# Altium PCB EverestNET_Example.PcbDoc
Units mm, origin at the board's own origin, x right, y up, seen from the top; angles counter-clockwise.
Board outline 100 x 100 mm, 6 copper layers (Top Layer, Mid-Layer 1, Mid-Layer 2, Mid-Layer 3, Mid-Layer 4, Bottom Layer), stack 1.62 mm thick; 18 components, 58 nets, 312 pads, 51 vias.
Unrouted connection lines stored in the file: 9.
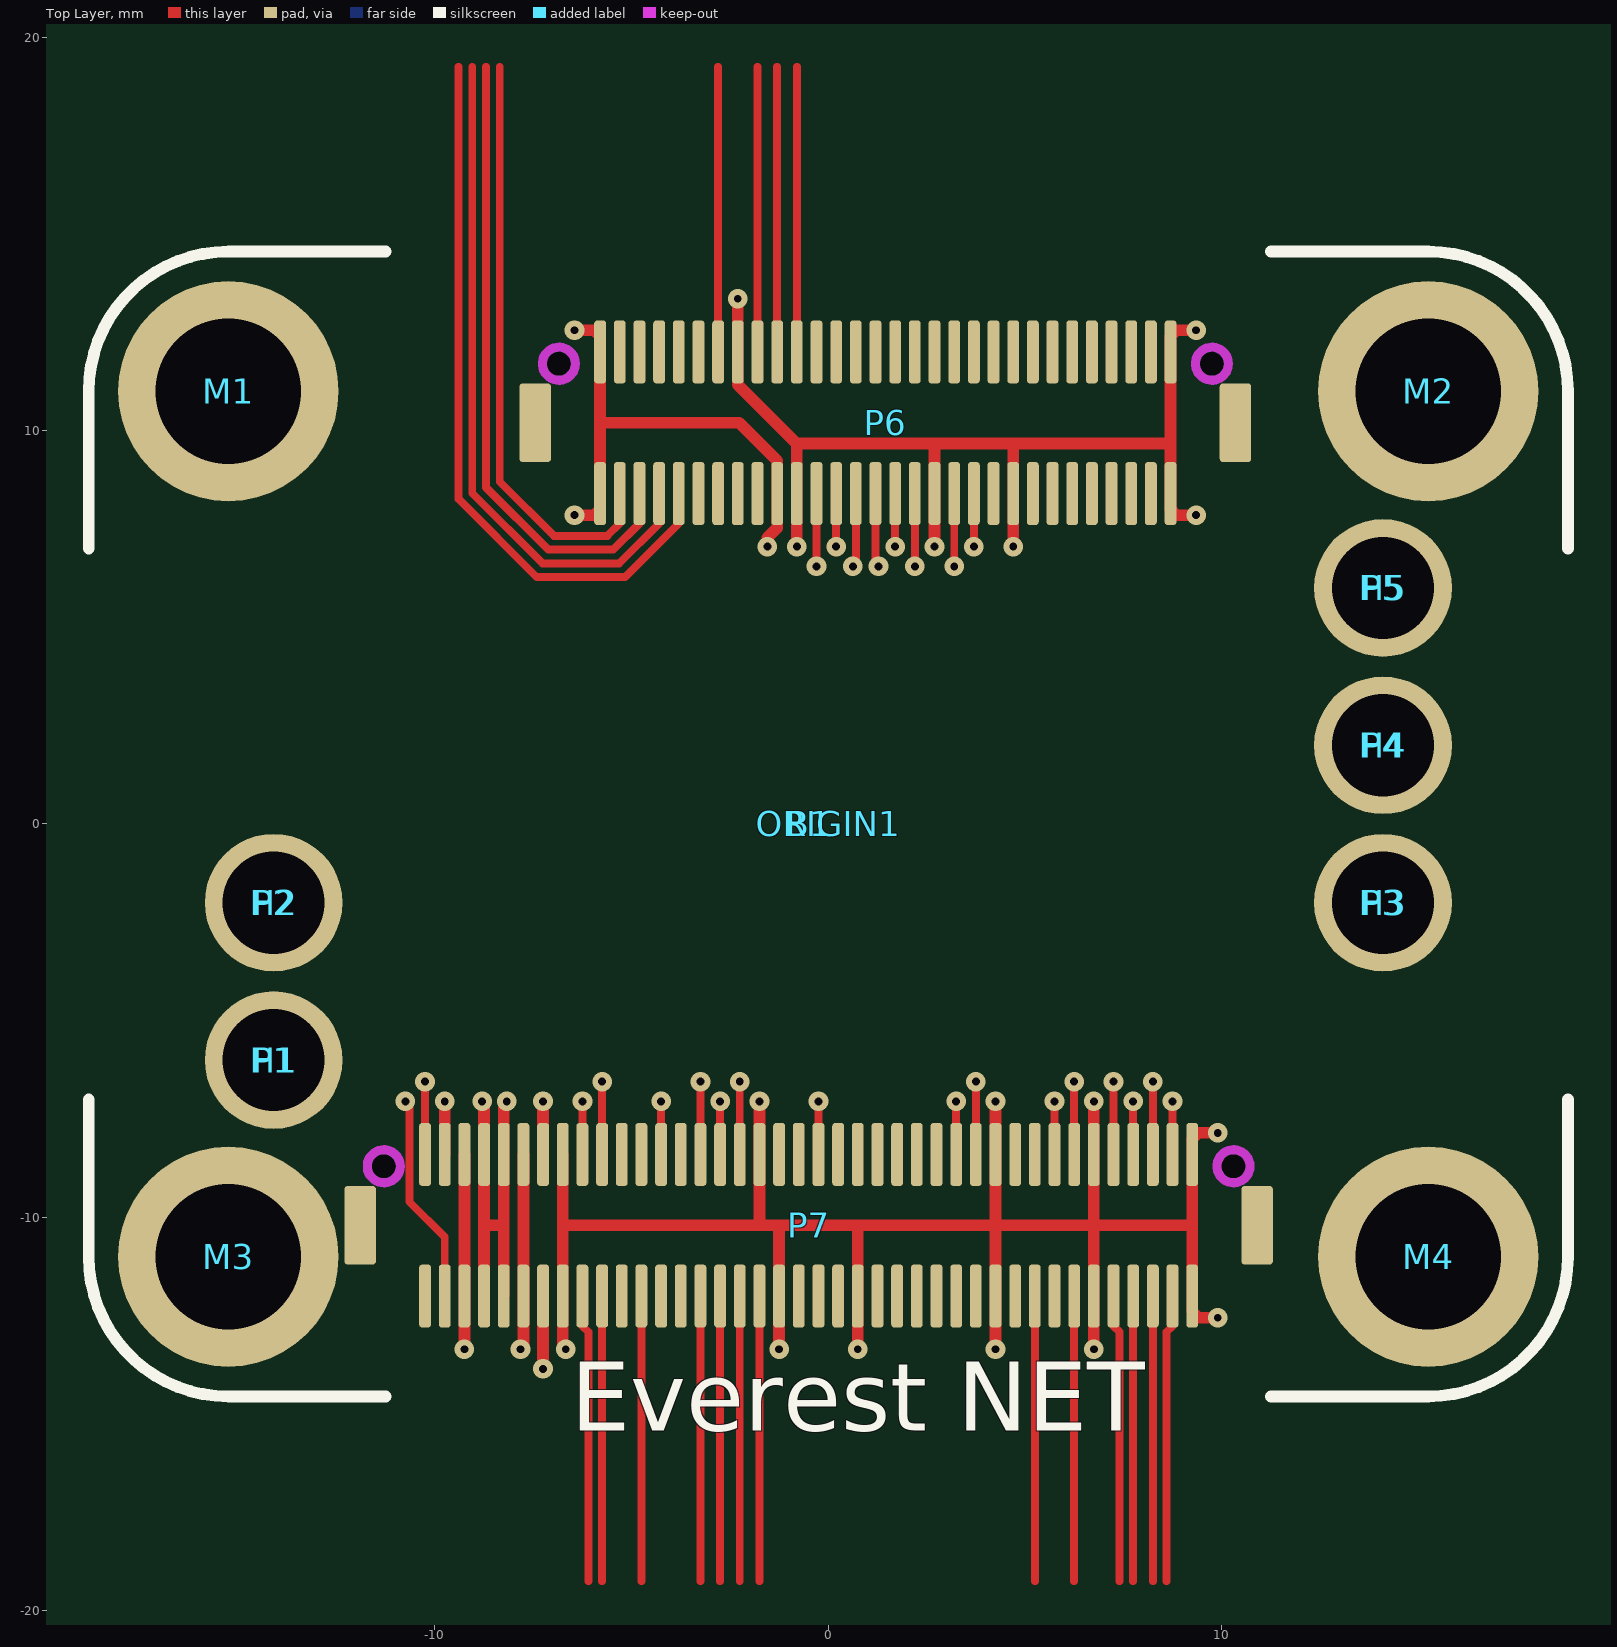
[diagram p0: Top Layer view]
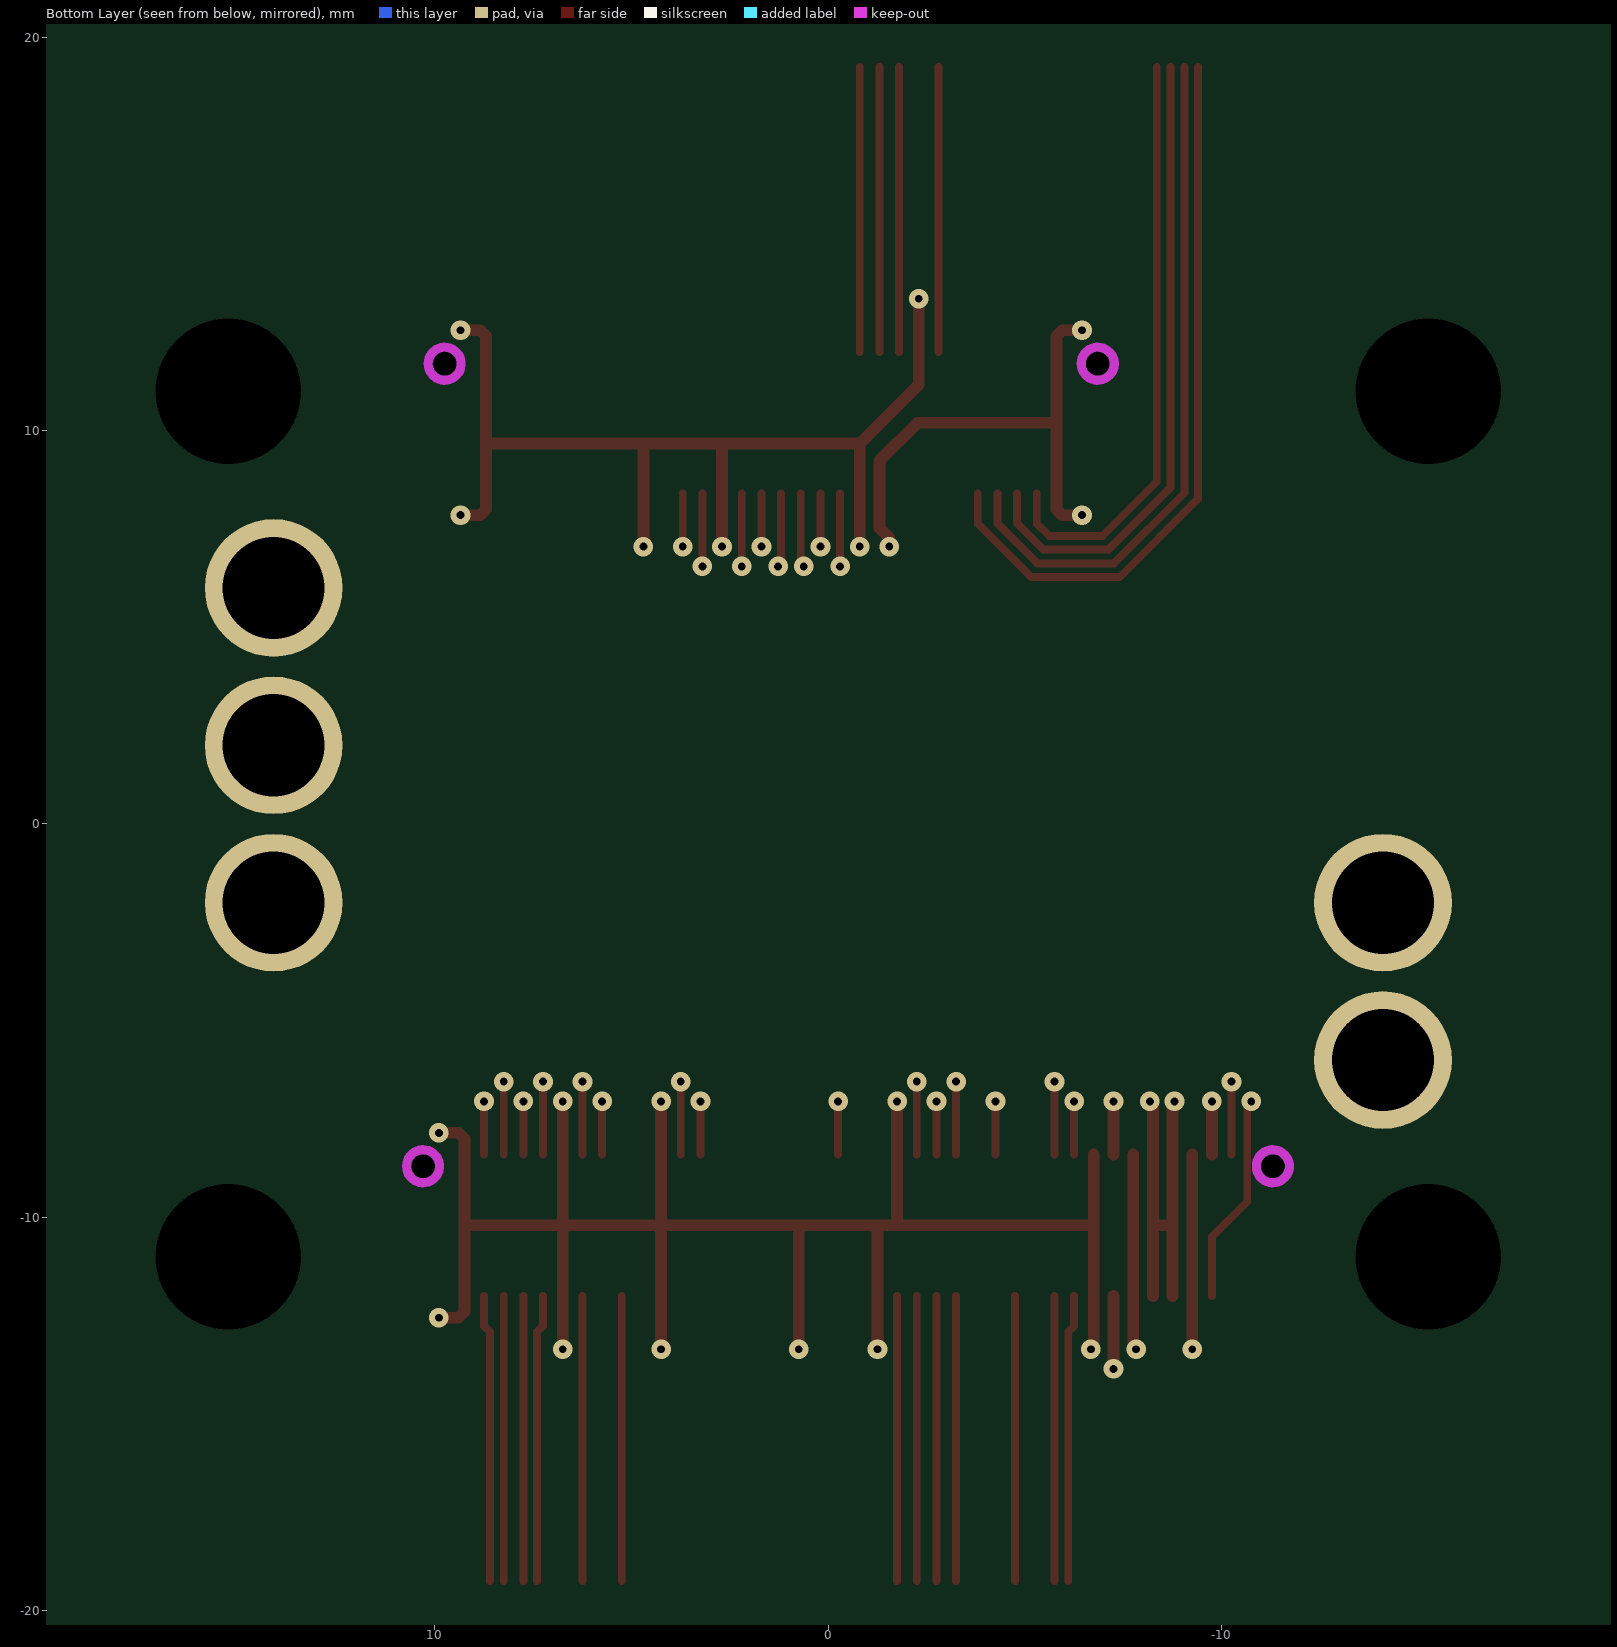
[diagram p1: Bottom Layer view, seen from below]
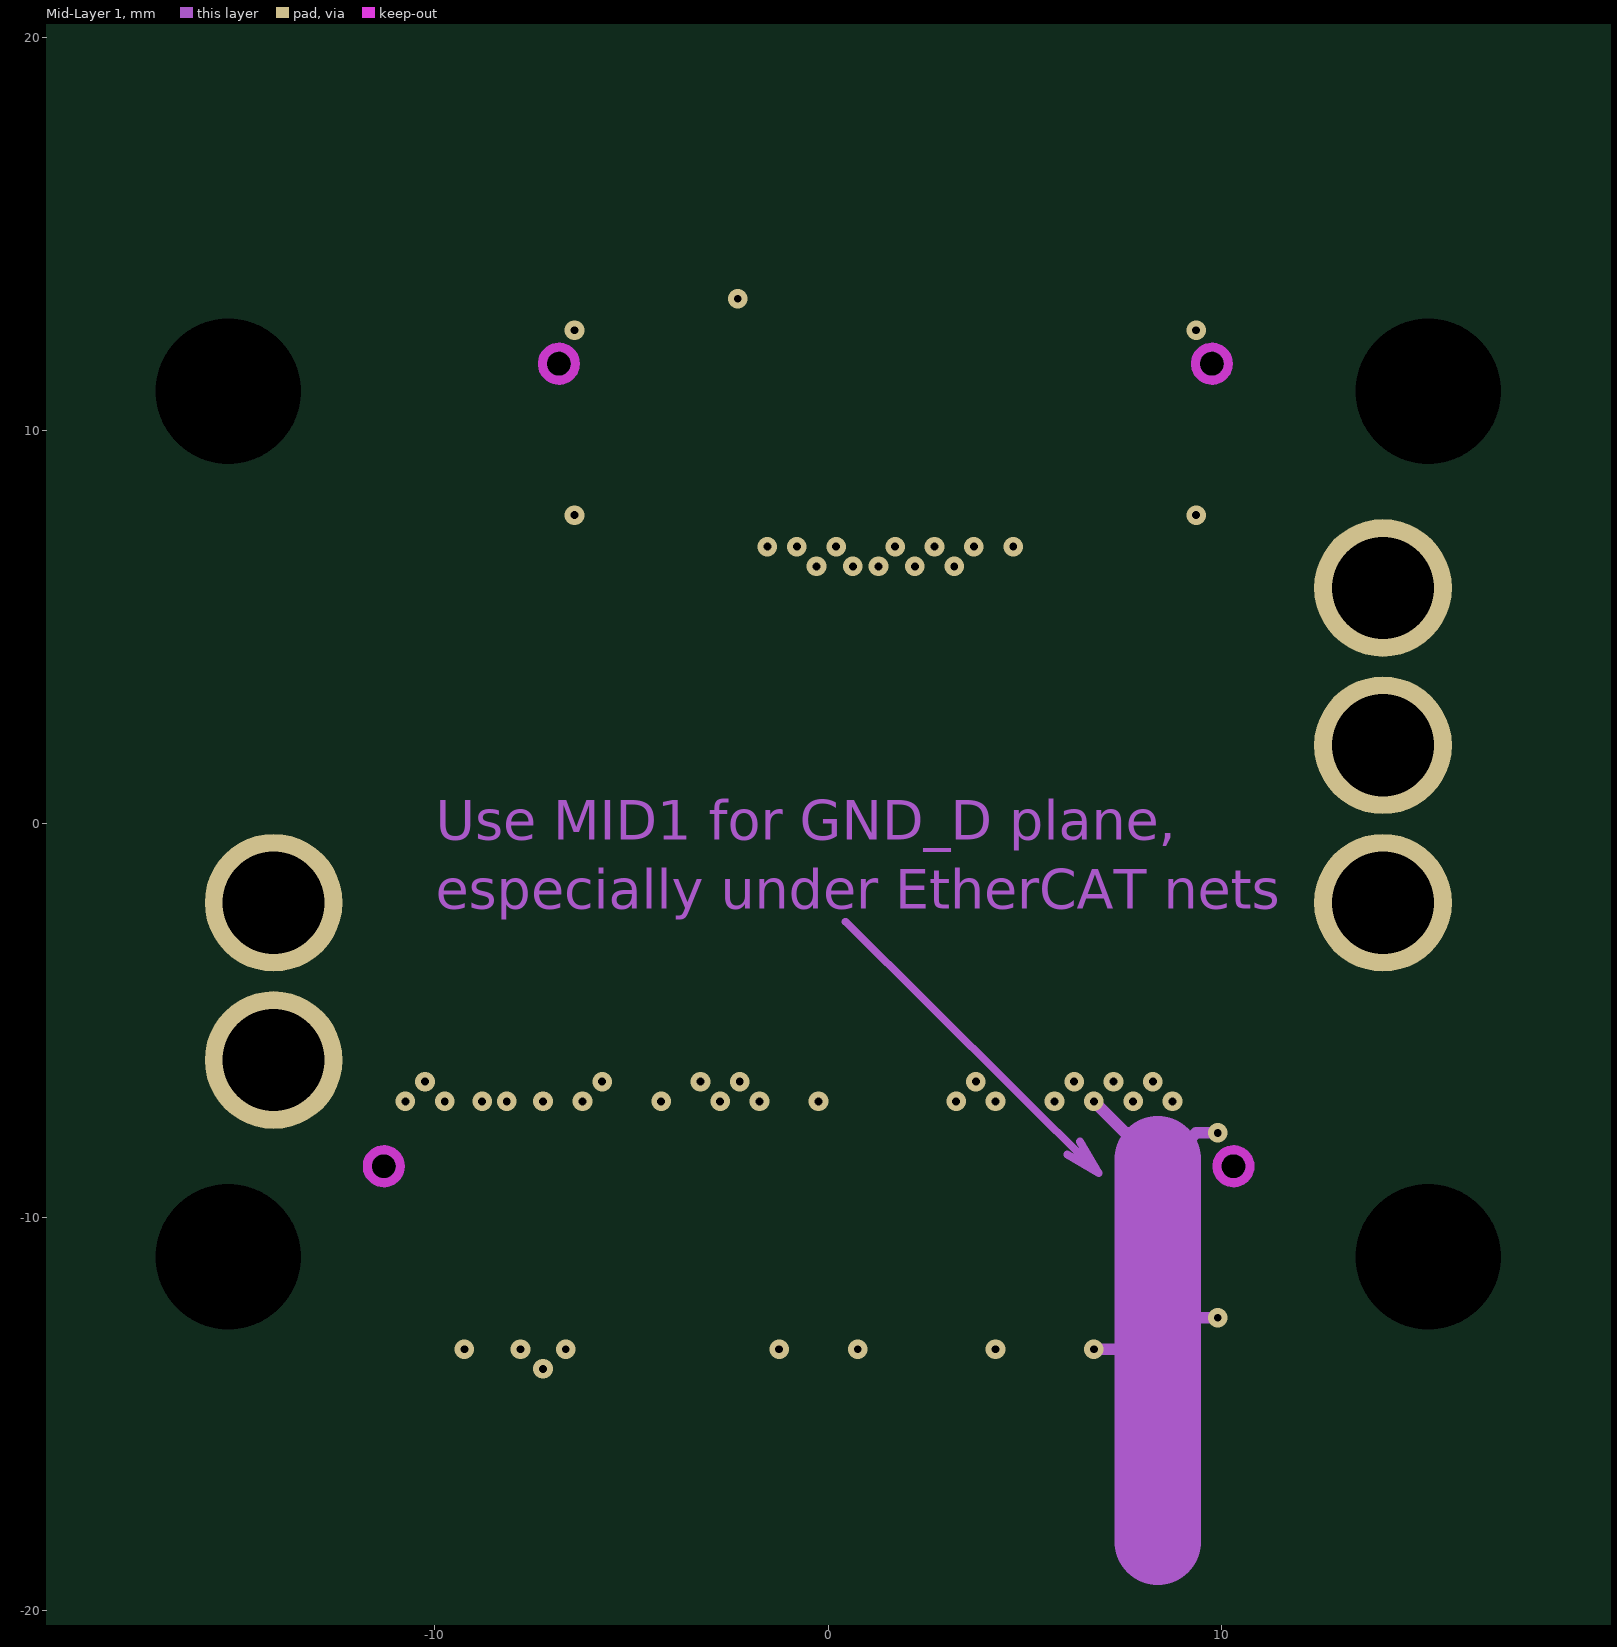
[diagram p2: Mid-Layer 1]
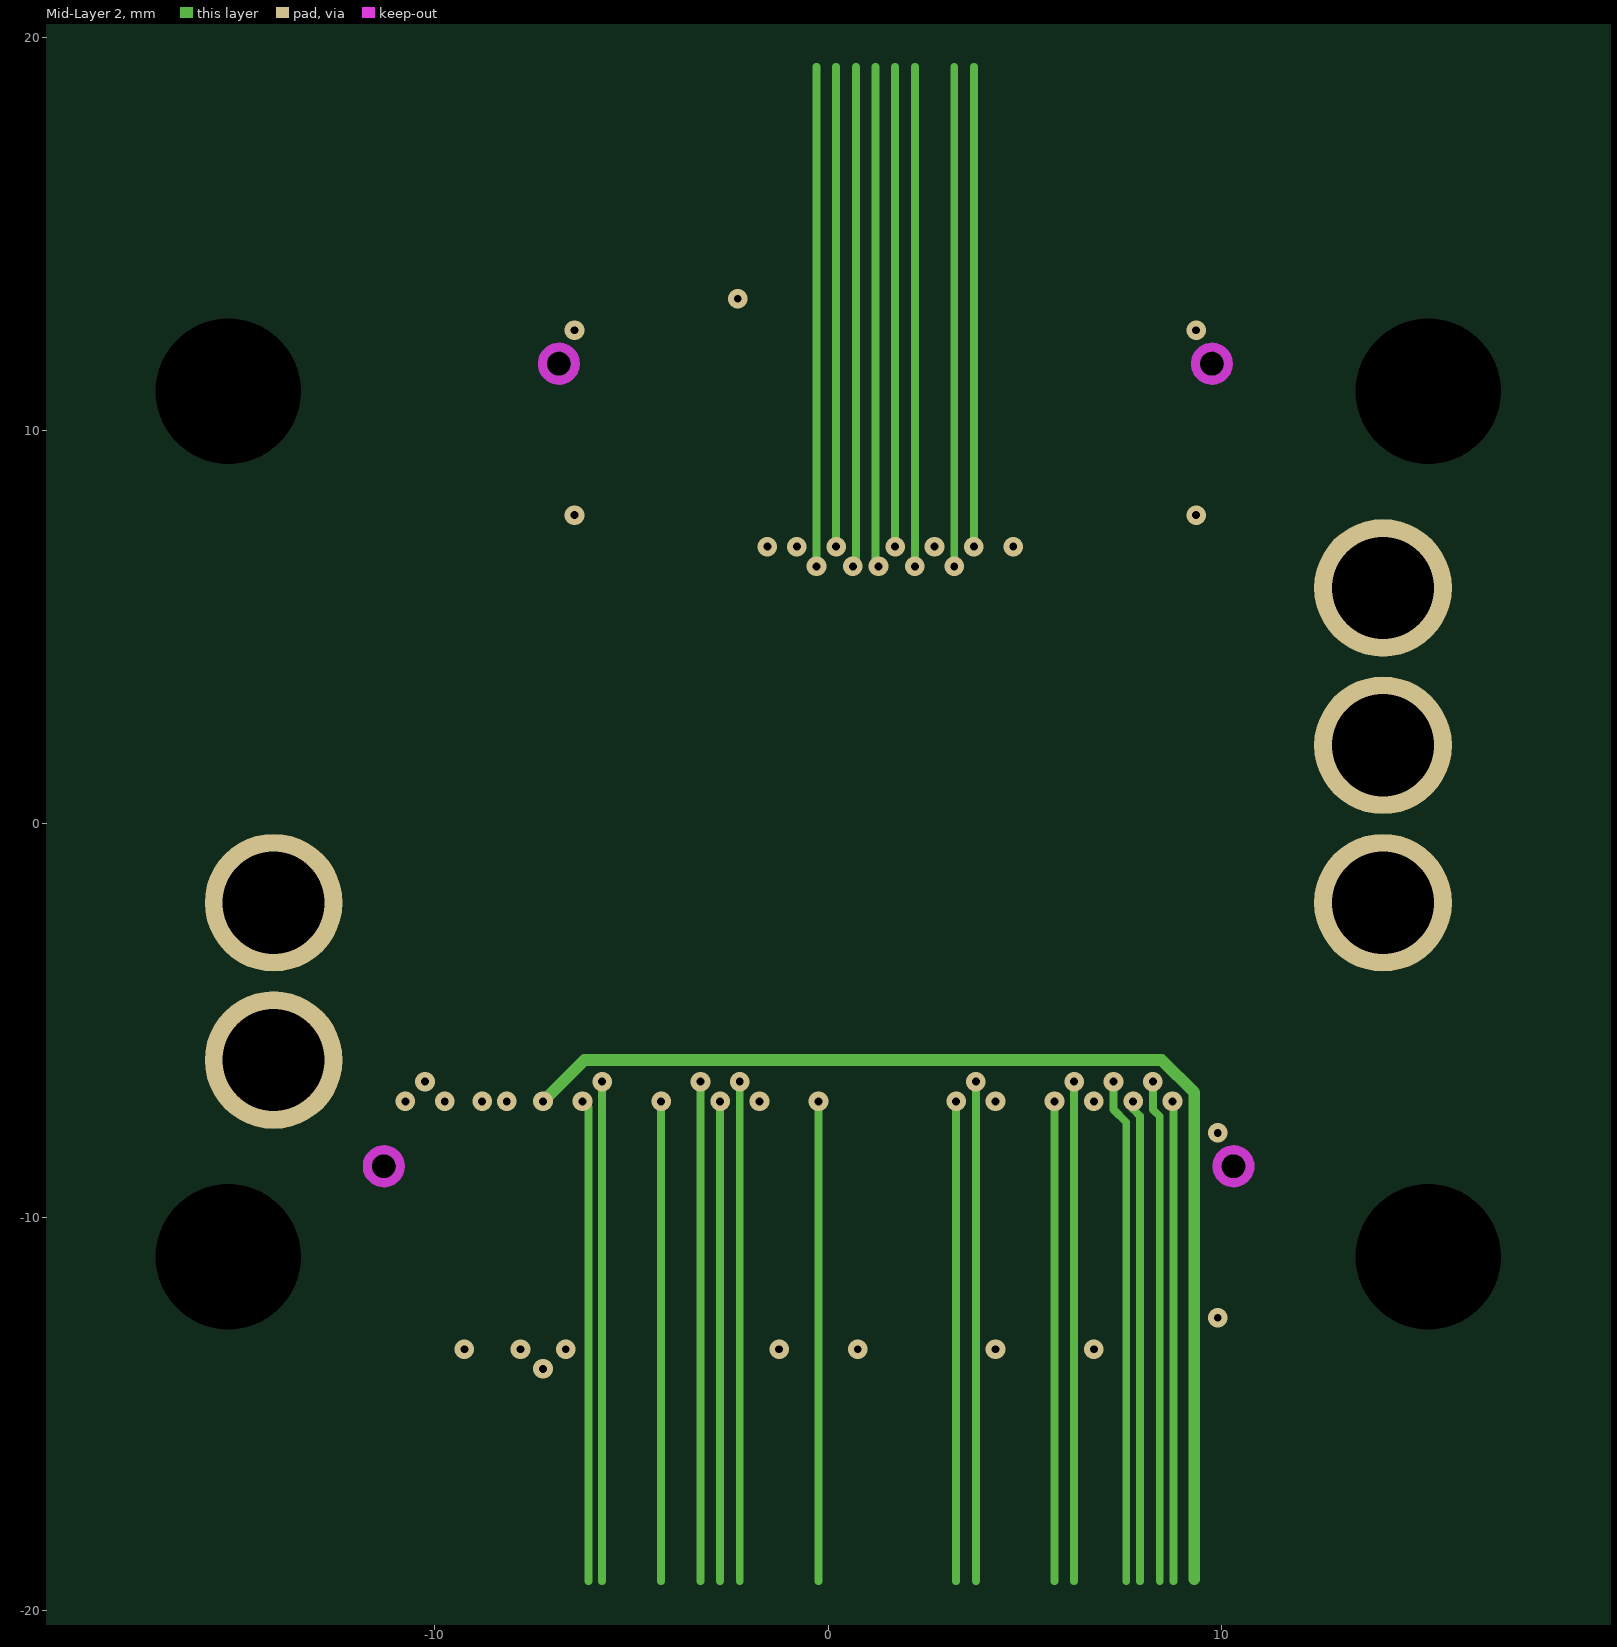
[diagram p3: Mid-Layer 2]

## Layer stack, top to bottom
Top Solder: solder mask 0.005, Solder Resist, Dk 3.5
Top Layer: signal copper 0.06
Dielectric 1: prepreg 0.22, FR-4 (tg > 150C), Dk 4.2
Mid-Layer 1: signal copper 0.035
Dielectric 2: core 0.35, FR-4 (tg > 150C), Dk 4.2
Mid-Layer 2: signal copper 0.035
Dielectric 3: prepreg 0.22, FR-4 (tg > 150C), Dk 4.2
Mid-Layer 3: signal copper 0.035
Dielectric 4: core 0.35, FR-4 (tg > 150C), Dk 4.2
Mid-Layer 4: signal copper 0.035
Dielectric 5: prepreg 0.22, FR-4 (tg > 150C), Dk 4.2
Bottom Layer: signal copper 0.06
Bottom Solder: solder mask 0.005, Solder Resist, Dk 3.5

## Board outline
-50.125,-47.425 49.875,-47.425 49.875,52.575 -50.125,52.575

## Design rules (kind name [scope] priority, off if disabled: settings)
AssemblyTestPointUsage [All] p1 off: valid=2
AssemblyTestpoint [All] p1 off: testpointundercomponent=TRUE minsize=1.016 maxsize=2.54 preferedsize=1.524 minholesize=0 maxholesize=1.016 preferedholesize=0.813 testpointgrid=0.025 usegrid=TRUE gridtolerance=0 allowsidetop=TRUE allowsidebottom=TRUE
Clearance "Keepout clearance" [All vs OnLayer('Keep-Out Layer') Or IsKeepOut Or Keepout] p1: gap=0.001 ignorepadtopadclearanceinfootprint=FALSE
Clearance HV [InNetClass('HighVoltage') vs OnOutside And NOT InNetClass('HighVoltageFloating')] p2: gap=0.5 ignorepadtopadclearanceinfootprint=TRUE
Clearance Clearance_PE [InNetClass('ProtectiveEarth')] p3: gap=0.5 ignorepadtopadclearanceinfootprint=TRUE
Clearance General [All] p4: gap=0.15 ignorepadtopadclearanceinfootprint=TRUE
ComponentClearance ComponentClearance_Excluded [All vs InComponent ('B1') OR InComponent('P1') OR InComponent('P2') OR InComponent('P3') OR InComponent('P4') OR InComponent('P5') OR InComponent('P6') OR InComponent('P7') OR InComponent('H1') OR InComponent('H2') OR InComponent('H3') OR InComponent('H4') OR InComponent('H5') OR InComponent('M1') OR InComponent('M2') OR InComponent('M3') OR InComponent('M4')] p1: gap=0 collisioncheckmode=3 verticalgap=0 showdistances=FALSE
ComponentClearance [All] p2: gap=0.2 collisioncheckmode=3 verticalgap=0.2 showdistances=FALSE
DiffPairsRouting [All] p1: maxlimit=1 minlimit=0.15 mostfreqgap=0.2 toplayer_minwidth=0.15 toplayer_maxwidth=0.3 toplayer_prefwidth=0.2 midlayer1_minwidth=0.15 midlayer1_maxwidth=0.3 midlayer1_prefwidth=0.2 midlayer2_minwidth=0.15 midlayer2_maxwidth=0.3 midlayer2_prefwidth=0.2 midlayer3_minwidth=0.15 midlayer3_maxwidth=0.3 midlayer3_prefwidth=0.2 midlayer4_minwidth=0.15 midlayer4_maxwidth=0.3 midlayer4_prefwidth=0.2 bottomlayer_minwidth=0.15 bottomlayer_maxwidth=0.3 bottomlayer_prefwidth=0.2 maxuncoupledlength=12.7
FabricationTestPointUsage [All] p1 off: valid=0 allowmultiple=FALSE
FabricationTestpoint [All] p1 off: side=3 testpointundercomponent=TRUE minsize=1.016 maxsize=2.54 preferedsize=1.524 minholesize=0 maxholesize=1.016 preferedholesize=0.813 testpointgrid=0.025 allowsidetop=TRUE allowsidebottom=TRUE usegrid=TRUE gridtolerance=0
FanoutControl Fanout_BGA [IsBGA] p1 off: bgadir=Out bgaviamode=Centered fanoutstyle=Auto fanoutdirection=Alternating viagrid=0.025 // Fanout_BGA (Default Rule)
FanoutControl Fanout_LCC [IsLCC] p2 off: bgadir=Out bgaviamode=Centered fanoutstyle=Auto fanoutdirection=Alternating viagrid=0.025 // Fanout_LCC (Default Rule)
FanoutControl Fanout_SOIC [IsSOIC] p3 off: bgadir=Out bgaviamode=Centered fanoutstyle=Auto fanoutdirection=Alternating viagrid=0.025 // Fanout_SOIC (Default Rule)
FanoutControl Fanout_Small [(CompPinCount < 5)] p4 off: bgadir=Out bgaviamode=Centered fanoutstyle=Auto fanoutdirection=OutThenIn viagrid=0.025 // Fanout_Small (Default Rule)
FanoutControl Fanout_Default [All] p5 off: bgadir=Out bgaviamode=Centered fanoutstyle=Auto fanoutdirection=Alternating viagrid=0.025 // Fanout_Default (Default Rule)
Height [All] p1: minheight=0 maxheight=30 prefheight=12.7
HoleSize [All] p1: absolutevalues=TRUE maxlimit=5 minlimit=0.1 maxpercent=80.000 minpercent=20.000
HoleToHoleClearance [All] p1: gap=0.3 allowstackedmicrovias=FALSE
MinimumAnnularRing [All] p1: minimumring=0.1
MinimumSolderMaskSliver [All] p1: minsoldermaskwidth=0.07
NetAntennae [All] p1: netantennaetolerance=2
PlaneClearance [All] p1: clearance=0.25
PlaneConnect [All] p1: planeconnectstyle=Relief reliefexpansion=0.5 reliefentries=4 reliefconductorwidth=0.25 reliefairgap=0.25
PolygonConnect [All] p1: connectstyle=Direct reliefconductorwidth=0.25 reliefentries=4 polygonreliefangle="90 Angle" airgapwidth=0.25
RoomDefinition U_EverestNET_Module [InComponentClass('U_EverestNET_Module')] p1: confinementstyle=ConfineIn formatcopy=TRUE lockcomponents=FALSE outline -129.505,-97.105 -78.705,-97.105 -78.705,-71.705 -129.505,-71.705
RoomDefinition Top [InComponentClass('Top')] p2 off: confinementstyle=ConfineIn formatcopy=TRUE lockcomponents=FALSE outline -129.505,-97.105 -78.705,-97.105 -78.705,-71.705 -129.505,-71.705
RoutingVias [All] p1: holewidth=0.2 width=0.6 viastyle="Through Hole" minholewidth=0.1 minwidth=0.3 maxholewidth=1 maxwidth=1.5
SilkToSilkClearance [All] p1 off: silktosilkclearance=0.1
SilkToSolderMaskClearance SilkscreenOverComponentPads [IsPad] p1 off: minsilkscreentomaskgap=0.05 clearancetoexposedcopper=TRUE
SolderMaskExpansion [All] p1: expansion=0.05
UnRoutedNet [All] p1: checkbadconnections=TRUE
Width [All] p1: maxlimit=80 minlimit=0.15 preferedwidth=0.2 checkconnectedcopper=TRUE
9 further rules are at their usual default settings.

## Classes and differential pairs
net class ProtectiveEarth: PE1 PE2 PE3 PE4
net class HighVoltage: GND_P PH_A PH_B PH_C POW_SUP
net class HighCurrent: GND_P PH_A PH_B PH_C POW_SUP
component class Top: FD9 FD10 H9 H10 H11 ORIGIN1 P? R42

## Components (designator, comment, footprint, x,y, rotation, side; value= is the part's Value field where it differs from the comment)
B1 "Everest_NET" EVEREST_NET 0,0 r0 top value=-
H1 "Part Number" Hole_1.7mm_Routing -14.1,-6 r0 top value=-
H2 "Part Number" Hole_1.7mm_Routing -14.1,-2 r0 top value=-
H3 "Part Number" Hole_1.7mm_Routing 14.1,-2 r0 top value=- (schematic designator H5)
H4 "Part Number" Hole_1.7mm_Routing 14.1,2 r0 top value=-
H5 "Part Number" Hole_1.7mm_Routing 14.1,6 r0 top value=- (schematic designator H3)
M1 "Part Number" WURTH_9774030951R_small -15.25,11 r0 top value=-
M2 "Part Number" WURTH_9774030951R_small 15.25,11 r0 top value=-
M3 "Part Number" WURTH_9774030951R_small -15.25,-11 r0 top value=-
M4 "WURTH_9774030951R" WURTH_9774030951R_small 15.25,-11 r0 top value=-
ORIGIN1 "ORIGIN" ORIGIN 0,0 r0 top locked value=-
P1 "Part Number" MillMax_9801-0-15-15-23-27-10-0 -14.1,-6 r0 top value=-
P2 "Part Number" MillMax_9801-0-15-15-23-27-10-0 -14.1,-2 r0 top value=-
P3 "Part Number" MillMax_9801-0-15-15-23-27-10-0 14.1,-2 r0 top value=- (schematic designator P5)
P4 "Part Number" MillMax_9801-0-15-15-23-27-10-0 14.1,2 r0 top value=-
P5 "Part Number" MillMax_9801-0-15-15-23-27-10-0 14.1,6 r0 top value=- (schematic designator P3)
P6 "HIROSE_DF12(3.0)-60DS-0.5V(86)" HIROSE_DF12(3.0)-60DS-0.5V(86) 1.45,10.2 r0 top value=-
P7 "HIROSE_DF12(3.0)-80DS-0.5V(86)" HIROSE_DF12(3.0)-80DS-0.5V(86) -0.5,-10.2 r0 top value=-

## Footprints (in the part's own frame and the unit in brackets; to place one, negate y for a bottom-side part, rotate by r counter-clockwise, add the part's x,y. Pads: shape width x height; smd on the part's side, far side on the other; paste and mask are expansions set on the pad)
EVEREST_NET [mm]
  rrect50% 0.8x2 on Mech5: 0(-11.9,-10.2) 0(-7.45,10.2) 0(10.35,10.2) 0(10.9,-10.2)
  rrect50% 0.3x1.6 on Mech5: 1(-10.25,-8.4) 1(-5.8,12) 2(-10.25,-12) 2(-5.8,8.4) 3(-9.75,-8.4) 3(-5.3,12) 4(-9.75,-12) 4(-5.3,8.4) 5(-9.25,-8.4) 5(-4.8,12) 6(-9.25,-12) 6(-4.8,8.4) 7(-8.75,-8.4) 7(-4.3,12) 8(-8.75,-12) 8(-4.3,8.4) 9(-8.25,-8.4) 9(-3.8,12) 10(-8.25,-12) 10(-3.8,8.4) 11(-7.75,-8.4) 11(-3.3,12) 12(-7.75,-12) 12(-3.3,8.4) 13(-7.25,-8.4) 13(-2.8,12) 14(-7.25,-12) 14(-2.8,8.4) 15(-6.75,-8.4) 15(-2.3,12) 16(-6.75,-12) 16(-2.3,8.4) 17(-6.25,-8.4) 17(-1.8,12) 18(-6.25,-12) 18(-1.8,8.4) 19(-5.75,-8.4) 19(-1.3,12) 20(-5.75,-12) 20(-1.3,8.4) 21(-5.25,-8.4) 21(-0.8,12) 22(-5.25,-12) 22(-0.8,8.4) 23(-4.75,-8.4) 23(-0.3,12) 24(-4.75,-12) 24(-0.3,8.4) 25(-4.25,-8.4) 25(0.2,12) 26(-4.25,-12) 26(0.2,8.4) 27(-3.75,-8.4) 27(0.7,12) 28(-3.75,-12) 28(0.7,8.4) 29(-3.25,-8.4) 29(1.2,12) 30(-3.25,-12) 30(1.2,8.4) 31(-2.75,-8.4) 31(1.7,12) 32(-2.75,-12) 32(1.7,8.4) 33(-2.25,-8.4) 33(2.2,12) 34(-2.25,-12) 34(2.2,8.4) 35(-1.75,-8.4) 35(2.7,12) 36(-1.75,-12) 36(2.7,8.4) 37(-1.25,-8.4) 37(3.2,12) 38(-1.25,-12) 38(3.2,8.4) 39(-0.75,-8.4) 39(3.7,12) 40(-0.75,-12) 40(3.7,8.4) 41(-0.25,-8.4) 41(4.2,12) 42(-0.25,-12) 42(4.2,8.4) 43(0.25,-8.4) 43(4.7,12) 44(0.25,-12) 44(4.7,8.4) 45(0.75,-8.4) 45(5.2,12) 46(0.75,-12) 46(5.2,8.4) 47(1.25,-8.4) 47(5.7,12) 48(1.25,-12) 48(5.7,8.4) 49(1.75,-8.4) 49(6.2,12) 50(1.75,-12) 50(6.2,8.4) 51(2.25,-8.4) 51(6.7,12) 52(2.25,-12) 52(6.7,8.4) 53(2.75,-8.4) 53(7.2,12) 54(2.75,-12) 54(7.2,8.4) 55(3.25,-8.4) 55(7.7,12) 56(3.25,-12) 56(7.7,8.4) 57(3.75,-8.4) 57(8.2,12) 58(3.75,-12) 58(8.2,8.4) 59(4.25,-8.4) 59(8.7,12) 60(4.25,-12) 60(8.7,8.4) 61(4.75,-8.4) 62(4.75,-12) 63(5.25,-8.4) 64(5.25,-12) 65(5.75,-8.4) 66(5.75,-12) 67(6.25,-8.4) 68(6.25,-12) 69(6.75,-8.4) 70(6.75,-12) 71(7.25,-8.4) 72(7.25,-12) 73(7.75,-8.4) 74(7.75,-12) 75(8.25,-8.4) 76(8.25,-12) 77(8.75,-8.4) 78(8.75,-12) 79(9.25,-8.4) 80(9.25,-12)
  silkscreen extent -18.8,-14.55 18.8,14.55, body extent -17.25,-13 17.25,13, height 14.95
HIROSE_DF12(3.0)-60DS-0.5V(86) [mm]
  rrect50% 0.3x1.6 smd: 1(-7.25,1.8) 2(-7.25,-1.8) 3(-6.75,1.8) 4(-6.75,-1.8) 5(-6.25,1.8) 6(-6.25,-1.8) 7(-5.75,1.8) 8(-5.75,-1.8) 9(-5.25,1.8) 10(-5.25,-1.8) 11(-4.75,1.8) 12(-4.75,-1.8) 13(-4.25,1.8) 14(-4.25,-1.8) 15(-3.75,1.8) 16(-3.75,-1.8) 17(-3.25,1.8) 18(-3.25,-1.8) 19(-2.75,1.8) 20(-2.75,-1.8) 21(-2.25,1.8) 22(-2.25,-1.8) 23(-1.75,1.8) 24(-1.75,-1.8) 25(-1.25,1.8) 26(-1.25,-1.8) 27(-0.75,1.8) 28(-0.75,-1.8) 29(-0.25,1.8) 30(-0.25,-1.8) 31(0.25,1.8) 32(0.25,-1.8) 33(0.75,1.8) 34(0.75,-1.8) 35(1.25,1.8) 36(1.25,-1.8) 37(1.75,1.8) 38(1.75,-1.8) 39(2.25,1.8) 40(2.25,-1.8) 41(2.75,1.8) 42(2.75,-1.8) 43(3.25,1.8) 44(3.25,-1.8) 45(3.75,1.8) 46(3.75,-1.8) 47(4.25,1.8) 48(4.25,-1.8) 49(4.75,1.8) 50(4.75,-1.8) 51(5.25,1.8) 52(5.25,-1.8) 53(5.75,1.8) 54(5.75,-1.8) 55(6.25,1.8) 56(6.25,-1.8) 57(6.75,1.8) 58(6.75,-1.8) 59(7.25,1.8) 60(7.25,-1.8)
  round 0 hole 0.6 unplated: H1(-8.3,1.5) H2(8.3,1.5)
  rrect20% 0.8x2 smd: S1(-8.9,0) S2(8.9,0)
  Keep-Out Layer circle w0.23: c8.3,1.5 r0.42
  Keep-Out Layer circle w0.23: c-8.3,1.5 r0.42
  body extent -9.05,-2.3 9.05,2.3, height 2.2
HIROSE_DF12(3.0)-80DS-0.5V(86) [mm]
  rrect50% 0.3x1.6 smd paste+0 mask+0.05: 1(-9.75,1.8) 2(-9.75,-1.8) 3(-9.25,1.8) 4(-9.25,-1.8) 5(-8.75,1.8) 6(-8.75,-1.8) 7(-8.25,1.8) 8(-8.25,-1.8) 9(-7.75,1.8) 10(-7.75,-1.8) 11(-7.25,1.8) 12(-7.25,-1.8) 13(-6.75,1.8) 14(-6.75,-1.8) 15(-6.25,1.8) 16(-6.25,-1.8) 17(-5.75,1.8) 18(-5.75,-1.8) 19(-5.25,1.8) 20(-5.25,-1.8) 21(-4.75,1.8) 22(-4.75,-1.8) 23(-4.25,1.8) 24(-4.25,-1.8) 25(-3.75,1.8) 26(-3.75,-1.8) 27(-3.25,1.8) 28(-3.25,-1.8) 29(-2.75,1.8) 30(-2.75,-1.8) 31(-2.25,1.8) 32(-2.25,-1.8) 33(-1.75,1.8) 34(-1.75,-1.8) 35(-1.25,1.8) 36(-1.25,-1.8) 37(-0.75,1.8) 38(-0.75,-1.8) 39(-0.25,1.8) 40(-0.25,-1.8) 41(0.25,1.8) 42(0.25,-1.8) 43(0.75,1.8) 44(0.75,-1.8) 45(1.25,1.8) 46(1.25,-1.8) 47(1.75,1.8) 48(1.75,-1.8) 49(2.25,1.8) 50(2.25,-1.8) 51(2.75,1.8) 52(2.75,-1.8) 53(3.25,1.8) 54(3.25,-1.8) 55(3.75,1.8) 56(3.75,-1.8) 57(4.25,1.8) 58(4.25,-1.8) 59(4.75,1.8) 60(4.75,-1.8) 61(5.25,1.8) 62(5.25,-1.8) 63(5.75,1.8) 64(5.75,-1.8) 65(6.25,1.8) 66(6.25,-1.8) 67(6.75,1.8) 68(6.75,-1.8) 69(7.25,1.8) 70(7.25,-1.8) 71(7.75,1.8) 72(7.75,-1.8) 73(8.25,1.8) 74(8.25,-1.8) 75(8.75,1.8) 76(8.75,-1.8) 77(9.25,1.8) 78(9.25,-1.8) 79(9.75,1.8) 80(9.75,-1.8)
  round 0 hole 0.6 unplated: H1(-10.8,1.5) H2(10.8,1.5)
  rrect20% 0.8x2 smd: S1(-11.4,0) S2(11.4,0)
  Keep-Out Layer circle w0.23: c10.8,1.5 r0.42
  Keep-Out Layer circle w0.23: c-10.8,1.5 r0.42
  body extent -11.55,-2.3 11.55,2.3, height 2.2
Hole_1.7mm_Routing [mm]
  round 2.7 hole 1.7 paste+0 mask+0.05: 1(0,0)
  Top Layer pour cut-out: 0,-0.8 -0.079,-0.8 -0.233,-0.769 -0.379,-0.709 -0.51,-0.621 -0.621,-0.51 -0.709,-0.379 -0.769,-0.233 -0.8,-0.079 -0.8,0 -0.8,0.079 -0.769,0.233 -0.709,0.379 -0.621,0.51 -0.51,0.621 -0.379,0.709 -0.233,0.769 -0.079,0.8 0,0.8 0.079,0.8 0.233,0.769 0.379,0.709 0.51,0.621 0.621,0.51 0.709,0.379 0.769,0.233 0.8,0.079 0.8,0 0.8,-0.079 0.769,-0.233 0.709,-0.379 0.621,-0.51 0.51,-0.621 0.379,-0.709 0.233,-0.769 0.079,-0.8 0,-0.8
  Top Layer pour cut-out: 0,-1.85 -0.182,-1.85 -0.54,-1.779 -0.876,-1.639 -1.179,-1.437 -1.437,-1.179 -1.639,-0.876 -1.779,-0.54 -1.85,-0.182 -1.85,0 -1.85,0.182 -1.779,0.54 -1.639,0.876 -1.437,1.179 -1.179,1.437 -0.876,1.639 -0.54,1.779 -0.182,1.85 0,1.85 0.182,1.85 0.54,1.779 0.876,1.639 1.179,1.437 1.437,1.179 1.639,0.876 1.779,0.54 1.85,0.182 1.85,0 1.85,-0.182 1.779,-0.54 1.639,-0.876 1.437,-1.179 1.179,-1.437 0.876,-1.639 0.54,-1.779 0.182,-1.85 0,-1.85
  Bottom Layer pour cut-out: 0,-0.8 -0.079,-0.8 -0.233,-0.769 -0.379,-0.709 -0.51,-0.621 -0.621,-0.51 -0.709,-0.379 -0.769,-0.233 -0.8,-0.079 -0.8,0 -0.8,0.079 -0.769,0.233 -0.709,0.379 -0.621,0.51 -0.51,0.621 -0.379,0.709 -0.233,0.769 -0.079,0.8 0,0.8 0.079,0.8 0.233,0.769 0.379,0.709 0.51,0.621 0.621,0.51 0.709,0.379 0.769,0.233 0.8,0.079 0.8,0 0.8,-0.079 0.769,-0.233 0.709,-0.379 0.621,-0.51 0.51,-0.621 0.379,-0.709 0.233,-0.769 0.079,-0.8 0,-0.8
  Bottom Layer pour cut-out: 0,-1.85 -0.182,-1.85 -0.54,-1.779 -0.876,-1.639 -1.179,-1.437 -1.437,-1.179 -1.639,-0.876 -1.779,-0.54 -1.85,-0.182 -1.85,0 -1.85,0.182 -1.779,0.54 -1.639,0.876 -1.437,1.179 -1.179,1.437 -0.876,1.639 -0.54,1.779 -0.182,1.85 0,1.85 0.182,1.85 0.54,1.779 0.876,1.639 1.179,1.437 1.437,1.179 1.639,0.876 1.779,0.54 1.85,0.182 1.85,0 1.85,-0.182 1.779,-0.54 1.639,-0.876 1.437,-1.179 1.179,-1.437 0.876,-1.639 0.54,-1.779 0.182,-1.85 0,-1.85
  body extent -0.01,-0.01 0.01,0.01, height 0.01
MillMax_9801-0-15-15-23-27-10-0 [mm]
  round 3.5 hole 2.6: 1(0,0)
  body extent -1.52,-1.52 1.52,1.52, height 1.78
ORIGIN [mm] "Origin of coordinate axes for pick and place"
  round 0.5 on Mech16 paste+0 mask+0: 1(0,0) 1(0,0)
  round 0.5 on Mech10 paste+0 mask+0: 1(0,0) 1(0,0)
  round 0.5 on Mech11 paste+0 mask+0: 1(0,0) 1(0,0)
  body extent 0,0 0,0
WURTH_9774030951R_small [mm]
  round 5.6 / inner round 0 / far side round 0 hole 3.7 unplated paste-403.566: 1(0,0)
  body extent -2.55,-2.55 2.55,2.55, height 3.01

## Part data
B1: library part EVEREST_NET, "Everest NET high-performance Servo Drive from Ingenia Motion Control.", ManufacturerName=Ingenia, ManufacturerPN=EVE-NET, Package Type=-, TemperatureMaxC=85, TemperatureMinC=-40
H1 H2 H3 H4 H5: library part Hole_1.7mm_Routing, "Mounting, plated hole, 1.7 mm diameter", ManufacturerName=Ingenia, ManufacturerPN=-, Package Type=NO, TemperatureMaxC=0
M1 M2 M3 M4: library part SPACER_RND_SMD_F, "Round SMD standoff M2.5 3mm height No Threaded Steel", ManufacturerName="Wurth Electronics Inc", ManufacturerPN=9774030951R, Package Name="SPACER M2.5 SMD REEL 3MM", Package Type=SM, Supplier Part Number 1=732-7086-1-ND, TemperatureMaxC=200, TemperatureMinC=-40
ORIGIN1: "Origin of coordinate axes for pick and place", ManufacturerName=-, TemperatureMaxC=200, TemperatureMinC=-60
P1 P2 P3 P4 P5: library part "Header 1", "1pin, receptacle for MillMax 6142, blind end", ManufacturerName=MillMax, ManufacturerPN=9801-0-15-15-23-27-10-0, Package Name=MillMax_9801-0-15-15-23-27-10-0, Package Type=TH, Supplier Part Number 1=ED1006-ND, TemperatureMaxC=125, TemperatureMinC=-55
P6: library part Header_30X2_MALE, "Connector SMD Mezzanine, 60 ways, 0.5mm pitch, 3mm stack height. Male", ManufacturerName=Hirose, ManufacturerPN=DF12(3.0)-60DS-0.5V(86), Package Name="SMD connector 60 ways", Package Type=SM, Supplier Part Number 1=H5207CT-ND, TemperatureMaxC=125, TemperatureMinC=-45
P7: library part Header_40x2_MALE, "Connector SMD Mezzanine, 80 ways, 0.5mm pitch, 3mm stack height. Male with metal fitting and boss", ManufacturerName=Hirose, ManufacturerPN=DF12(3.0)-80DS-0.5V(86), Package Name="SMD connector 80 ways male", Package Type=SM, Supplier Part Number 1=H5208CT-ND, TemperatureMaxC=125, TemperatureMinC=-45

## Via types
v1: diameter 0.5, hole 0.2, Top Layer to Bottom Layer, 51 vias

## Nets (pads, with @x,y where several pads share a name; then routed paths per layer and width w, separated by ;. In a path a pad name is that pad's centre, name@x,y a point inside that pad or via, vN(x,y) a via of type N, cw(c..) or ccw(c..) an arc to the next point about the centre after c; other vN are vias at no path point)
+1.65V_REF: P7.4 | length 5.4
  Top Layer w0.2: v1(-10.75,-7.05) -10.65,-7.15 -10.65,-9.6 -9.75,-10.5 P7.4
+3.3V_D: P6.25 P6.29 P7.14 | length 1.8
  Top Layer w0.3: v1(-7.25,-13.85) P7.14
+3.3V_REF: P7.1 | length 1.8
  Top Layer w0.2: P7.1 v1(-10.25,-6.55)
+5V_D: P7.7 P7.8 P7.9 P7.10 | length 10.4
  Top Layer w0.3: P7.8 -8.75,-10.2 ; v1@-8.75,-7.05 P7.7 -8.75,-10.2 ; P7.10 -8.25,-10.2 ; v1@-8.25,-7.05 P7.9 -8.25,-10.2 ; -8.75,-10.2 -8.25,-10.2
  other v1: -8.8,-7.05 -8.175,-7.05
\ETH0_LED_LINK: P7.67 | length 14.5
  Top Layer w0.2: P7.67 v1(6.25,-6.55)
  Mid-Layer 2 w0.2: 6.25,-19.25 v1(6.25,-6.55)
\ETH1_LED_LINK: P7.68 | length 7.3
  Top Layer w0.2: 6.25,-19.25 P7.68
\STO1: P7.33 | length 14.5
  Top Layer w0.2: P7.33 v1(-2.25,-6.55)
  Mid-Layer 2 w0.2: -2.25,-19.25 v1(-2.25,-6.55)
\STO2: P7.34 | length 7.3
  Top Layer w0.2: -2.25,-19.25 P7.34
ABSENC1_CLK: P6.38 | length 14.5
  Top Layer w0.2: v1(3.2,6.55) P6.38
  Mid-Layer 2 w0.2: v1(3.2,6.55) 3.2,19.25
ABSENC1_DATA: P6.40 | length 13.5
  Top Layer w0.2: v1(3.7,7.05) P6.40
  Mid-Layer 2 w0.2: v1(3.7,7.05) 3.7,19.25
ABSENC2_CLK: P7.24 | length 7.3
  Top Layer w0.2: -4.75,-19.25 P7.24
ABSENC2_DATA: P7.25 | length 13.5
  Top Layer w0.2: P7.25 v1(-4.25,-7.05)
  Mid-Layer 2 w0.2: -4.25,-19.25 v1(-4.25,-7.05)
AN1_N: P6.6 | length 16.3
  Top Layer w0.2: -8.7,19.25 -8.7,8.555 -7.12,6.975 -5.465,6.975 -4.8,7.64 P6.6
AN1_P: P6.4 | length 15.1
  Top Layer w0.2: -8.35,19.25 -8.35,8.7 -6.975,7.325 -5.615,7.325 -5.3,7.64 P6.4
CAN_RX: P7.57 | length 14.5
  Top Layer w0.2: P7.57 v1(3.75,-6.55)
  Mid-Layer 2 w0.2: 3.75,-19.25 v1(3.75,-6.55)
CAN_TX: P7.55 | length 13.5
  Top Layer w0.2: P7.55 v1(3.25,-7.05)
  Mid-Layer 2 w0.2: 3.25,-19.25 v1(3.25,-7.05)
DIG_ENC_1A: P6.24 | length 14.5
  Top Layer w0.2: v1(-0.3,6.55) P6.24
  Mid-Layer 2 w0.2: v1(-0.3,6.55) -0.3,19.25
DIG_ENC_1B: P6.26 | length 13.5
  Top Layer w0.2: v1(0.2,7.05) P6.26
  Mid-Layer 2 w0.2: v1(0.2,7.05) 0.2,19.25
DIG_ENC_1Z: P6.28 | length 14.6
  Top Layer w0.2: v1(0.625,6.55) 0.7,6.625 P6.28
  Mid-Layer 2 w0.2: v1(0.625,6.55) 0.7,6.625 0.7,19.25
DIG_ENC_2A: P6.30 | length 14.6
  Top Layer w0.2: P6.30 1.2,6.625 v1(1.275,6.55)
  Mid-Layer 2 w0.2: 1.2,19.25 1.2,6.625 v1(1.275,6.55)
DIG_ENC_2B: P6.32 | length 13.5
  Top Layer w0.2: v1(1.7,7.05) P6.32
  Mid-Layer 2 w0.2: v1(1.7,7.05) 1.7,19.25
DIG_ENC_2Z: P6.34 | length 14.5
  Top Layer w0.2: v1(2.2,6.55) P6.34
  Mid-Layer 2 w0.2: v1(2.2,6.55) 2.2,19.25
ECAT_CAN_ERR: P7.64 | length 7.3
  Top Layer w0.2: 5.25,-19.25 P7.64
ECAT_CAN_RUN: P7.65 | length 13.5
  Top Layer w0.2: P7.65 v1(5.75,-7.05)
  Mid-Layer 2 w0.2: 5.75,-19.25 v1(5.75,-7.05)
FAULT_SIGNAL: P7.36 | length 7.3
  Top Layer w0.2: -1.75,-19.25 P7.36
GND_A: P6.1 P6.2 P6.20 P7.3 | length 14.4
  Top Layer w0.3: P7.3 v1(-9.75,-7.05) ; v1(-6.45,7.85) -5.95,7.85 -5.8,8 P6.2 -5.8,10.2 ; v1(-6.45,12.55) -5.95,12.55 -5.8,12.4 P6.1 -5.8,10.2 ; v1(-1.55,7.05) -1.55,7.275 -1.3,7.525 P6.20 -1.3,9.23 -2.27,10.2 -5.8,10.2
GND_D: P6.15 P6.22 P6.23 P6.27 P6.36 P6.44 P6.59 P6.60 P7.5 P7.6 P7.11 P7.12 P7.15 P7.16 P7.35 P7.38 P7.46 P7.59 P7.60 P7.69 P7.70 P7.79 P7.80 | length 103.7
  Top Layer w0.3: v1(-9.25,-13.35) P7.5 ; v1(-7.825,-13.35) -7.825,-13.296 -7.75,-13.221 P7.12 P7.11 ; P7.15 -6.75,-10.2 ; v1(-6.675,-13.35) -6.675,-13.296 -6.75,-13.221 P7.16 -6.75,-10.2 ; v1(-2.3,13.35) P6.15 -2.3,11.17 -0.8,9.67 ; v1(-1.75,-7.05) -1.75,-10.2 ; v1(-1.25,-13.35) -1.25,-10.2 ; v1(-0.8,7.05) P6.22 -0.8,9.67 ; v1(0.75,-13.35) 0.75,-10.2 ; v1(2.7,7.05) P6.36 2.7,9.67 ; v1(4.25,-13.35) 4.25,-10.2 ; 4.25,-10.15 v1(4.25,-7.05) ; v1(4.7,7.05) P6.44 4.7,9.67 ; v1(6.75,-13.35) 6.75,-10.2 ; v1(6.75,-7.05) 6.75,-10.2 ; v1(9.35,7.85) 8.85,7.85 8.7,8 P6.60 8.7,9.67 ; v1(9.35,12.55) 8.85,12.55 8.7,12.4 P6.59 8.7,9.67 ; v1(9.9,-12.55) 9.4,-12.55 9.25,-12.4 9.25,-10.2 ; v1(9.9,-7.85) 9.4,-7.85 9.25,-8 9.25,-10.2 ; -6.75,-10.2 -1.75,-10.2 ; -1.75,-10.2 -1.25,-10.2 ; -1.25,-10.2 0.75,-10.2 ; -0.8,9.67 2.7,9.67 ; 0.75,-10.2 4.25,-10.2 ; 2.7,9.67 4.7,9.67 ; 4.25,-10.2 6.75,-10.2 ; 4.7,9.67 8.7,9.67 ; 6.75,-10.2 9.25,-10.2
  Mid-Layer 1 w0.3: v1(6.75,-13.35) 7.45,-13.35 8.25,-12.55 8.375,-12.55 v1(9.9,-12.55) ; v1(6.75,-7.05) 7.55,-7.85 8.138,-7.85 8.744,-8.456 9.35,-7.85 v1(9.9,-7.85)
  Mid-Layer 1 w2.2: 8.375,-18.25 8.375,-12.7 ; 8.375,-12.975 8.375,-12.55 8.375,-8.525
GND_P: H2.1 P2.1
GPI1: P7.18 | length 7.3
  Top Layer w0.2: P7.18 -6.25,-12.76 -6.1,-12.91 -6.1,-19.25
GPI2: P7.19 | length 14.5
  Top Layer w0.2: P7.19 v1(-5.75,-6.55)
  Mid-Layer 2 w0.2: -5.75,-19.25 v1(-5.75,-6.55)
GPI3: P7.20 | length 7.3
  Top Layer w0.2: -5.75,-19.25 P7.20
GPI4: P7.32 | length 7.3
  Top Layer w0.2: -2.75,-19.25 P7.32
GPO1: P7.29 | length 14.5
  Top Layer w0.2: P7.29 v1(-3.25,-6.55)
  Mid-Layer 2 w0.2: -3.25,-19.25 v1(-3.25,-6.55)
GPO2: P7.30 | length 7.3
  Top Layer w0.2: -3.25,-19.25 P7.30
GPO3: P7.31 | length 13.5
  Top Layer w0.2: P7.31 v1(-2.75,-7.05)
  Mid-Layer 2 w0.2: -2.75,-19.25 v1(-2.75,-7.05)
GPO4: P7.17 | length 13.6
  Top Layer w0.2: P7.17 v1(-6.25,-7.05)
  Mid-Layer 2 w0.2: v1(-6.25,-7.05) -6.1,-7.2 -6.1,-19.25
HALL_1: P6.17 | length 7.3
  Top Layer w0.2: P6.17 -1.8,19.25
HALL_2: P6.19 | length 7.3
  Top Layer w0.2: P6.19 -1.3,19.25
HALL_3: P6.21 | length 7.3
  Top Layer w0.2: P6.21 -0.8,19.25
MAGNETICS_CT: P7.13 | length 31.1
  Top Layer w0.3: P7.13 v1(-7.25,-7.05)
  Mid-Layer 2 w0.3: v1(-7.25,-7.05) -6.2,-6 8.478,-6 9.3,-6.822 9.3,-19.2
MOTOR_TEMP: P6.13 | length 7.3
  Top Layer w0.2: P6.13 -2.8,19.25
PE1: M1.1
PE2: M2.1
PE3: M3.1 P7.S1
PE4: M4.1
PH_A: H3.1 P3.1
PH_B: H4.1 P4.1
PH_C: H5.1 P5.1
PHY0_RX_N: P7.77 | length 13.4
  Top Layer w0.2: P7.77 v1(8.75,-7.05)
  Mid-Layer 2 w0.2: v1@8.75,-7.131 v1(8.75,-7.05) ; 8.775,-19.25 v1@8.775,-7.281
PHY0_RX_P: P7.75 | length 14.6
  Top Layer w0.2: P7.75 v1(8.25,-6.55)
  Mid-Layer 2 w0.2: v1(8.25,-6.55) 8.25,-7.257 8.425,-7.432 8.425,-19.25
PHY0_TX_N: P7.73 | length 13.6
  Top Layer w0.2: P7.73 v1(7.75,-7.05)
  Mid-Layer 2 w0.2: v1(7.75,-7.05) 7.75,-7.252 7.925,-7.427 7.925,-19.25
PHY0_TX_P: P7.71 | length 14.7
  Top Layer w0.2: P7.71 v1(7.25,-6.55)
  Mid-Layer 2 w0.2: v1(7.25,-6.55) 7.25,-7.257 7.575,-7.582 7.575,-19.25
PHY1_RX_N: P7.78 | length 7.3
  Top Layer w0.2: 8.6,-19.25 8.6,-12.91 8.75,-12.76 P7.78
PHY1_RX_P: P7.76 | length 7.3
  Top Layer w0.2: 8.25,-19.25 P7.76
PHY1_TX_N: P7.74 | length 7.3
  Top Layer w0.2: 7.75,-19.25 P7.74
PHY1_TX_P: P7.72 | length 7.3
  Top Layer w0.2: P7.72 7.25,-12.76 7.4,-12.91 7.4,-19.25
POW_SUP: H1.1 P1.1
PWM_BRAKE: P7.41 | length 13.5
  Top Layer w0.2: P7.41 v1(-0.25,-7.05)
  Mid-Layer 2 w0.2: -0.25,-19.25 v1(-0.25,-7.05)
pads on no net: B1.0 B1.1 B1.2 B1.3 B1.4 B1.5 B1.6 B1.7 B1.8 B1.9 B1.10 B1.11 B1.12 B1.13 B1.14 B1.15 B1.16 B1.17 B1.18 B1.19 B1.20 B1.21 B1.22 B1.23 B1.24 B1.25 B1.26 B1.27 B1.28 B1.29 B1.30 B1.31 B1.32 B1.33 B1.34 B1.35 B1.36 B1.37 B1.38 B1.39 B1.40 B1.41 B1.42 B1.43 B1.44 B1.45 B1.46 B1.47 B1.48 B1.49 B1.50 B1.51 B1.52 B1.53 B1.54 B1.55 B1.56 B1.57 B1.58 B1.59 B1.60 B1.61 B1.62 B1.63 B1.64 B1.65 B1.66 B1.67 B1.68 B1.69 B1.70 B1.71 B1.72 B1.73 B1.74 B1.75 B1.76 B1.77 B1.78 B1.79 B1.80 ORIGIN1.1 P6.3 P6.5 P6.7 P6.8 P6.9 P6.10 P6.11 P6.12 P6.14 P6.16 P6.18 P6.31 P6.33 P6.35 P6.37 P6.39 P6.41 P6.42 P6.43 P6.45 P6.46 P6.47 P6.48 P6.49 P6.50 P6.51 P6.52 P6.53 P6.54 P6.55 P6.56 P6.57 P6.58 P6.H1 P6.H2 P6.S1 P6.S2 P7.2 P7.21 P7.22 P7.23 P7.26 P7.27 P7.28 P7.37 P7.39 P7.40 P7.42 P7.43 P7.44 P7.45 P7.47 P7.48 P7.49 P7.50 P7.51 P7.52 P7.53 P7.54 P7.56 P7.58 P7.61 P7.62 P7.63 P7.66 P7.H1 P7.H2 P7.S2
copper on no net: | length 47.2
  Top Layer w0.2: -9.4,19.25 -9.4,8.265 -7.41,6.275 -5.165,6.275 -3.8,7.64 -3.8,8.4 ; -9.05,19.25 -9.05,8.41 -7.265,6.625 -5.315,6.625 -4.3,7.64 -4.3,8.4
  Mid-Layer 1 w0.2: 0.44,-2.485 6.875,-8.875 ; 6.075,-8.4 6.875,-8.875 ; 6.4,-8.075 6.875,-8.875

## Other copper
Mid-Layer 1:
  text "Use MID1 for GND_D plane," at -9.975,-0.4 h1
  text "especially under EtherCAT nets" at -9.975,-2.15 h1

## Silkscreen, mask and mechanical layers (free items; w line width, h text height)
Drill Drawing:
  circle w0.254: c-43.668,29.937 r0.462
  lines w0.2: -44.996,26.771 44.983,26.771 ; -44.996,37.171 44.983,37.171 ; -39.651,24.691 -39.651,39.251 ; -35.25,24.691 -35.25,39.251 ; -25.563,24.691 -25.563,39.251 ; -21.419,24.691 -21.419,39.251 ; -15.386,24.691 -15.386,39.251 ; -3.949,24.691 -3.949,39.251 ; 0.994,24.691 0.994,39.251 ; 7.452,24.691 7.452,39.251 ; 17.975,24.691 17.975,39.251 ; 24.46,24.691 24.46,39.251 ; 34.545,24.691 34.545,39.251 ; -44.996,24.691 44.983,24.691 44.983,39.251 -44.996,39.251 -44.996,24.691
  lines w0.254: -44.13,27.395 -43.668,27.626 -43.206,27.395 -43.437,27.857 -43.206,28.319 -43.668,28.088 -44.13,28.319 -43.899,27.857 -44.13,27.395 ; -44.13,31.786 -43.899,31.786 -43.668,31.555 -43.437,31.786 -43.206,31.786 -43.437,32.017 -43.206,32.248 -43.437,32.248 -43.668,32.48 -43.899,32.248 -44.13,32.248 -43.899,32.017 -44.13,31.786 ; -44.13,34.56 -43.206,34.56 -43.668,33.635 -44.13,34.56 ; -44.13,35.715 -43.206,35.715 -43.206,36.64 -44.13,36.64 -44.13,35.715
  text "Symbol" at -43.748,37.795 h1.21
  text "Count" at -39.027,37.795 h1.21
  text "Hole Size" at -34.626,37.795 h1.21
  text "Plated" at -24.939,37.795 h1.21
  text "Hole Type" at -20.795,37.795 h1.21
  text "Drill Layer Pair" at -14.762,37.795 h1.21
  text "Via/Pad" at -3.325,37.795 h1.21
  text "Pad Shape" at 1.618,37.795 h1.21
  text "Template" at 8.076,37.795 h1.21
  text "Description" at 18.599,37.795 h1.21
  text "Hole Tolerance (+)" at 25.084,37.795 h1.21
  text "Hole Tolerance (-)" at 35.169,37.795 h1.21
  text "4" at -39.027,35.715 h1
  text "0,600mm (23,62mil)" at -34.626,35.715 h1
  text "NPTH" at -24.939,35.715 h1
  text "Round" at -20.795,35.715 h1
  text "Top Layer - Bottom Layer" at -14.762,35.715 h1
  text "Pad" at -3.325,35.715 h1
  text "Rounded" at 1.618,35.715 h1
  text "c0hn60" at 8.076,35.715 h1
  text "4" at -39.027,33.635 h1
  text "3,700mm (145,67mil)" at -34.626,33.635 h1
  text "NPTH" at -24.939,33.635 h1
  text "Round" at -20.795,33.635 h1
  text "Top Layer - Bottom Layer" at -14.762,33.635 h1
  text "Pad" at -3.325,33.635 h1
  text "Rounded" at 1.618,33.635 h1
  text "c560hn370z0x0p40917" at 8.076,33.635 h1
  text "5" at -39.027,31.555 h1
  text "1,700mm (66,93mil)" at -34.626,31.555 h1
  text "PTH" at -24.939,31.555 h1
  text "Round" at -20.795,31.555 h1
  text "Top Layer - Bottom Layer" at -14.762,31.555 h1
  text "Pad" at -3.325,31.555 h1
  text "Rounded" at 1.618,31.555 h1
  text "c270h170m275p270" at 8.076,31.555 h1
  text "5" at -39.027,29.475 h1
  text "2,600mm (102,36mil)" at -34.626,29.475 h1
  text "PTH" at -24.939,29.475 h1
  text "Round" at -20.795,29.475 h1
  text "Top Layer - Bottom Layer" at -14.762,29.475 h1
  text "Pad" at -3.325,29.475 h1
  text "Rounded" at 1.618,29.475 h1
  text "c350h260" at 8.076,29.475 h1
  text "51" at -39.027,27.395 h1
  text "0,200mm (7,87mil)" at -34.626,27.395 h1
  text "PTH" at -24.939,27.395 h1
  text "Round" at -20.795,27.395 h1
  text "Top Layer - Bottom Layer" at -14.762,27.395 h1
  text "Via" at -3.325,27.395 h1
  text "Rounded" at 1.618,27.395 h1
  text "v50h20m40" at 8.076,27.395 h1
  text "69 Total" at -39.027,25.315 h1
